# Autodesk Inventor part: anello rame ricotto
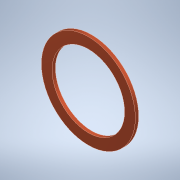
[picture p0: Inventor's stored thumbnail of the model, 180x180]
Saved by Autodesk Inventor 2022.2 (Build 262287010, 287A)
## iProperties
Created: 2022-03
Part Number: anello rame ricotto
Material: Rame
Document SubType Name: Modeling
Designer: 18619647
Density: 8.94 g/cm^3
Appearance: Rame - Satinato
Author: 18619647
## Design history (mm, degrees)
sketch "Schizzo1"
  geometry: C1 r 11 at (0, 0); C2 r 14.25 at (0, 0); 1 further point
  constraints: 2 centre point, 2 coincident
  dimensions: "d0" = 22 diameter of C1; "d1" = 28.5 diameter of C2
extrude "Estrusione1" new body sketch "Schizzo1" distance "d2" = 1; taper "d3" = 0 deg
node "Solido1"
